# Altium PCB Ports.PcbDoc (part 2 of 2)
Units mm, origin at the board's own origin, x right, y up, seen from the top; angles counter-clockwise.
Board outline 100.96 x 99.82 mm, 2 copper layers (Top Layer, Bottom Layer); 116 components, 156 nets, 535 pads, 185 vias.
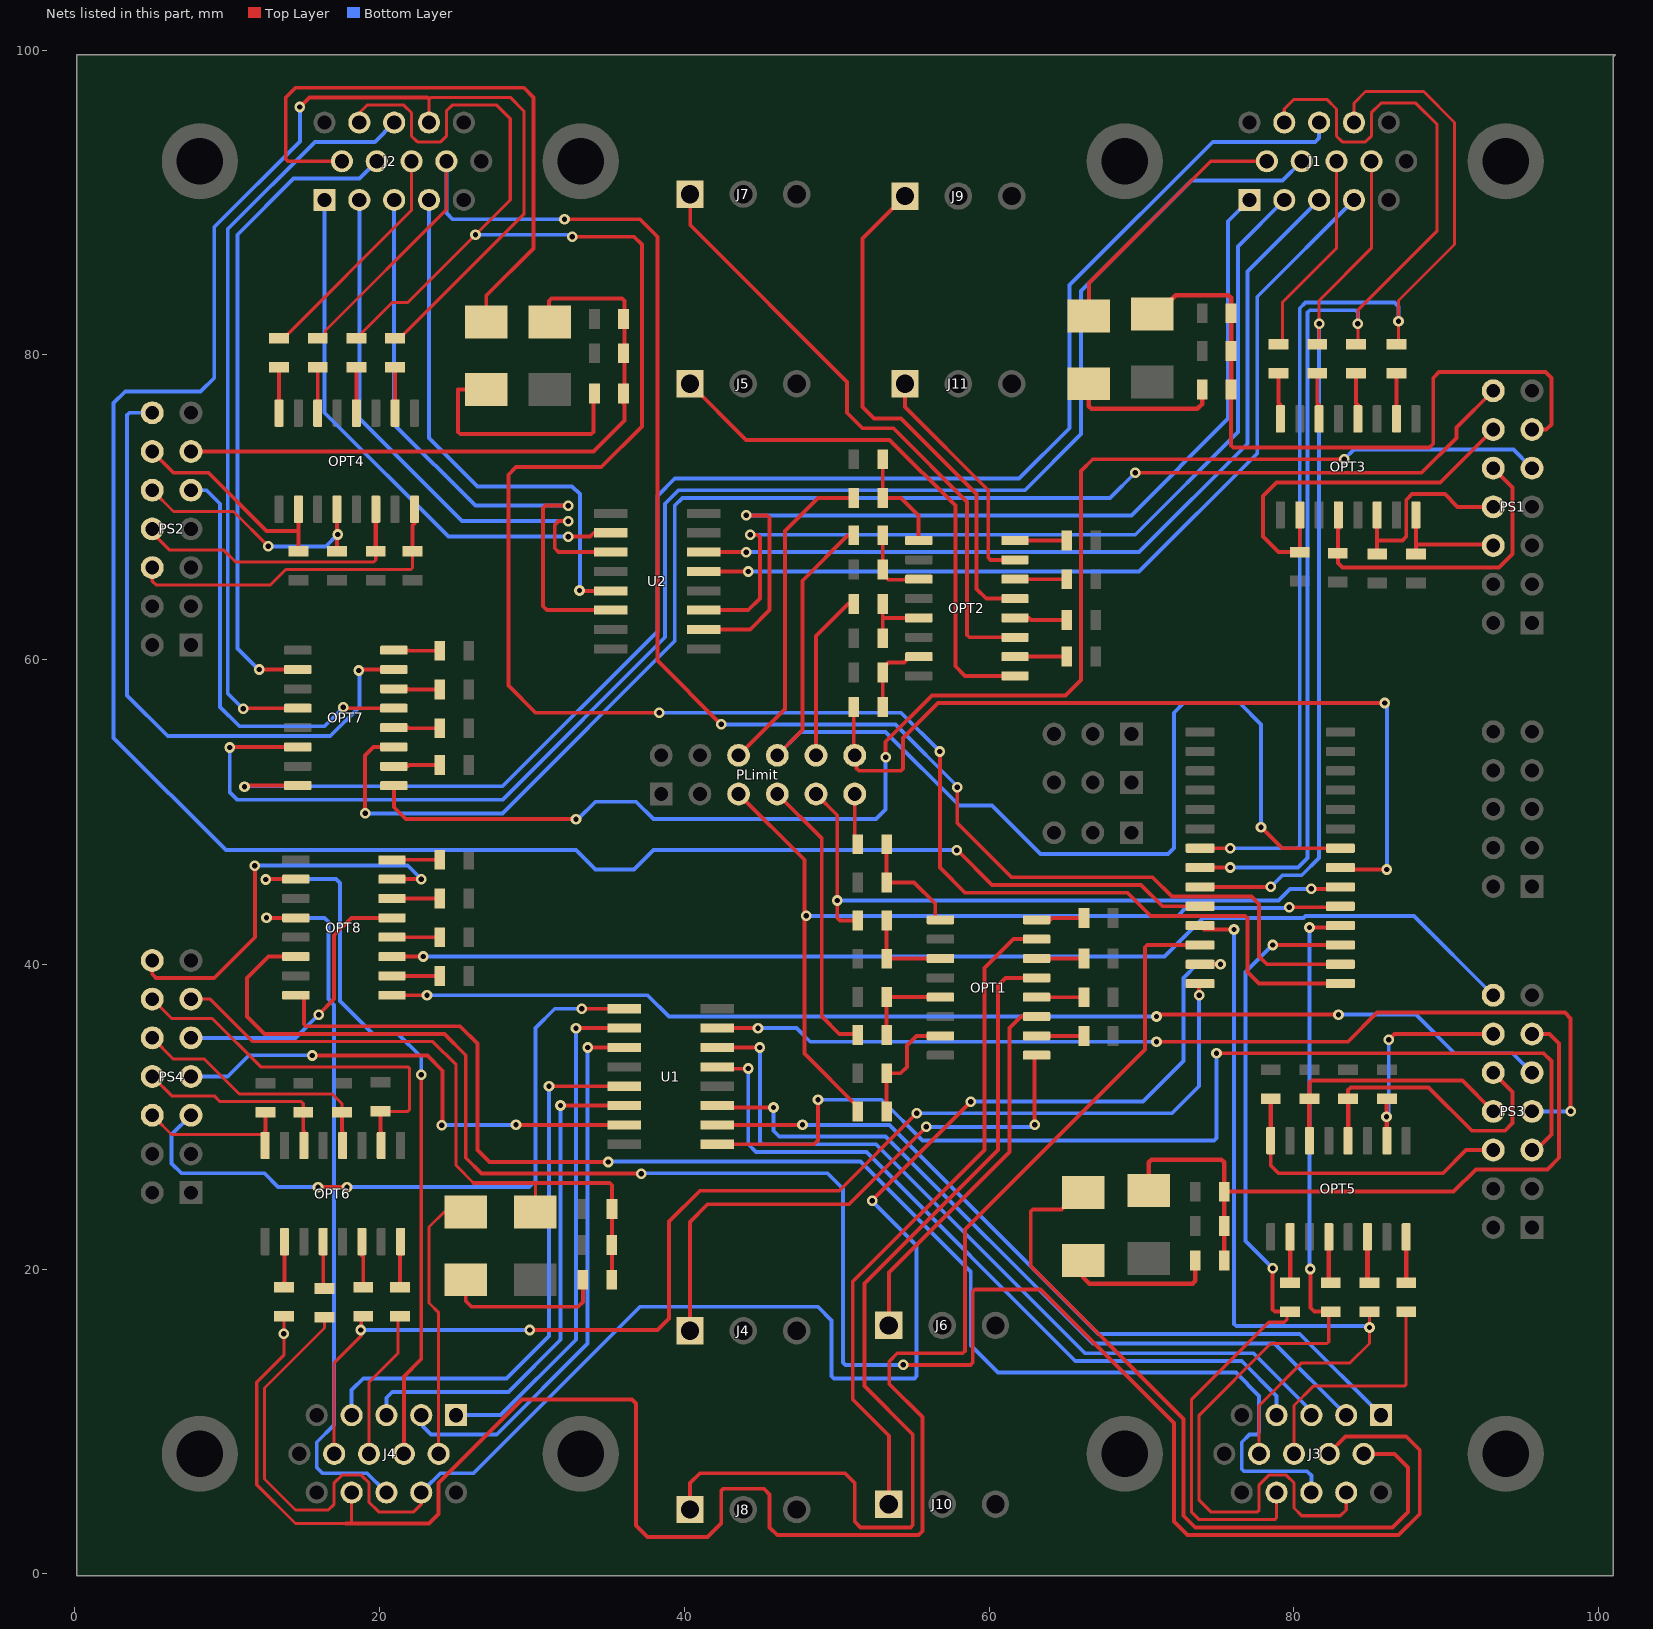
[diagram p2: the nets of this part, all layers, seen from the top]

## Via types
v1: diameter 0.7, hole 0.35, Top Layer to Bottom Layer, 151 vias
v2: diameter 0.9, hole 0.711, Top Layer to Bottom Layer, 29 vias
v3: diameter 4, hole 3, Top Layer to Bottom Layer, 4 vias
v4: diameter 1.27, hole 0.711, Top Layer to Bottom Layer, 1 vias

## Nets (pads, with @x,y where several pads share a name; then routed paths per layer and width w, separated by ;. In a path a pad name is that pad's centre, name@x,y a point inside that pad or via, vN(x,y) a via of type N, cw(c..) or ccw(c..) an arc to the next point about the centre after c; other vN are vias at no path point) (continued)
MCU_S3_DR: PS3.7 U1.7 | length 66
  Top Layer w0.254: U1.7@42.164,35.814 v1(44.831,35.814) ; v1(70.993,34.925) 83.566,34.925 85.471,36.83 97.79,36.83 98.171,36.449 v1(98.171,30.353)
  Bottom Layer w0.254: v1(44.831,35.814) 47.371,35.814 48.26,34.925 v1(70.993,34.925) ; PS3.7@95.631,30.353 v1(98.171,30.353)
MCU_S3_PLS: PS3.5 U1.1 | length 70.7
  Top Layer w0.254: U1.1@42.164,28.194 48.514,28.194 48.768,28.448 v1(48.768,31.115) ; v1(74.93,34.163) 96.393,34.163 96.901,33.655 96.901,28.829 PS3.5@95.885,27.813
  Bottom Layer w0.254: v1(48.768,31.115) 52.959,31.115 55.626,28.448 74.781,28.448 74.93,28.597 v1(74.93,34.163)
MCU_S4_DR: PS4.7 U1.15 | length 33.1
  Top Layer w0.254: v1(15.575,34.014) 23.136,34.014 24.13,33.02 v1@24.13,29.464 ; v1(28.956,29.464) U1.15@36.064,29.464
  Bottom Layer w0.254: PS4.7@7.62,32.639 10.033,32.639 11.43,34.036 15.553,34.036 v1(15.575,34.014) ; v1(24.084,29.442) 24.107,29.464 v1(28.956,29.464)
MCU_S4_PLS: PS4.5 U1.9 | length 44.7
  Top Layer w0.254: v1(15.956,25.378) 15.979,25.4 v1@17.78,25.4 ; v1(33.274,37.084) U1.9@36.064,37.084
  Bottom Layer w0.254: PS4.5@7.62,30.099 6.35,28.829 6.35,26.924 6.985,26.289 12.446,26.289 13.335,25.4 15.934,25.4 v1(15.956,25.378) ; v1(17.861,25.378) 29.823,25.378 30.226,25.781 30.226,35.814 31.496,37.084 v1(33.274,37.084)
NetD5_2: D5.2 R57.2 | length 10.1
  Top Layer w0.3: D5.2@66.548,78.105 66.548,76.63 66.724,76.454 73.66,76.454 73.98,76.774 R57.2@73.98,77.724
NetD6_2: D6.2 R58.2 | length 16.3
  Top Layer w0.254: D6.2@26.998,77.724 25.146,77.724 25.146,74.952 25.295,74.803 33.887,74.803 34.036,74.952 R58.2@34.036,77.644
NetD7_2: D7.2 R59.2 | length 10.1
  Top Layer w0.3: D7.2@66.167,20.574 66.167,19.469 66.585,19.051 73.356,19.051 73.532,19.227 R59.2@73.532,20.574
NetD8_2: D8.2 R60.2 | length 10.8
  Top Layer w0.254: D8.2@25.654,19.304 25.654,17.907 26.035,17.526 33.02,17.526 33.34,17.846 R60.2@33.34,19.304
NetJ4_1: J4.1@40.371,15.951 OPT1.1 | length 37
  Top Layer w0.254: J4.1@40.371,15.951 40.371,23.099 41.529,24.257 50.8,24.257 v1(55.88,29.337) ; v1(62.992,29.464) 62.992,33.909 OPT1.1@63.119,34.036
  Bottom Layer w0.254: v1(55.88,29.337) 62.865,29.337 v1(62.992,29.464)
NetJ5_1: J5.1 OPT2.1 | length 35.4
  Top Layer w0.254: J5.1@40.371,78.105 44.054,74.422 53.467,74.422 57.785,70.104 57.785,59.563 58.42,58.928 OPT2.1@61.702,58.928
NetJ6_1: J6.1 OPT1.3 | length 24.9
  Top Layer w0.254: J6.1@53.421,16.301 53.421,19.766 61.341,27.686 61.341,35.814 62.103,36.576 OPT1.3@63.119,36.576
NetJ7_1: J7.1 OPT2.3 | length 40.9
  Top Layer w0.254: J7.1@40.371,90.551 40.386,90.536 40.386,88.519 50.673,78.232 50.673,76.2 51.689,75.184 53.721,75.184 58.547,70.358 58.547,61.617 58.696,61.468 OPT2.3@61.702,61.468
NetJ8_1: J8.1 OPT1.5 | length 62.4
  Top Layer w0.254: J8.1@40.371,4.572 40.371,5.954 41.021,6.604 50.546,6.604 51.181,5.969 51.181,3.429 51.562,3.048 54.842,3.048 54.991,3.197 54.991,9.144 51.816,12.319 51.816,19.05 60.579,27.813 60.579,38.608 61.087,39.116 OPT1.5@63.119,39.116
NetJ9_1: J9.1 OPT2.5 | length 33.9
  Top Layer w0.254: J9.1@54.483,90.424 51.689,87.63 51.689,76.581 52.451,75.819 54.229,75.819 59.182,70.866 59.182,64.643 59.817,64.008 OPT2.5@61.702,64.008
NetJ10_1: J10.1 OPT1.7 | length 44
  Top Layer w0.254: J10.1@53.421,4.572 53.421,9.063 51.054,11.43 51.054,19.177 59.69,27.813 59.69,39.751 61.595,41.656 OPT1.7@63.119,41.656
NetJ11_1: J11.1 OPT2.7 | length 15.5
  Top Layer w0.254: J11.1@54.483,78.105 54.483,76.581 59.944,71.12 59.944,66.697 60.093,66.548 OPT2.7@61.702,66.548
NetOPT1_2: OPT1.2 R1.2 | length 3.1
  Top Layer w0.254: OPT1.2@63.119,35.306 64.307,35.306 R1.2@66.233,35.306
NetOPT1_4: OPT1.4 R5.2 | length 3.1
  Top Layer w0.254: OPT1.4@63.119,37.846 R5.2@66.233,37.846
NetOPT1_6: OPT1.6 R9.2 | length 3.1
  Top Layer w0.254: OPT1.6@63.119,40.386 R9.2@66.233,40.386
NetOPT1_8: OPT1.8 R14.2 | length 3.2
  Top Layer w0.254: OPT1.8@63.119,42.926 64.044,42.926 64.171,43.053 R14.2@66.233,43.053
NetOPT1_9: OPT1.9 R13.1 R71.1 | length 7.6
  Top Layer w0.254: R71.1@53.274,47.879 53.274,46.051 R13.1@53.274,45.375 55.082,45.375 56.471,43.986 56.471,43.094 56.639,42.926 OPT1.9@56.809,42.926
NetOPT1_11: OPT1.11 R10.1 R68.1 | length 6
  Top Layer w0.254: R68.1@53.274,42.872 R10.1@53.274,40.368 53.649,40.368 53.668,40.386 OPT1.11@56.809,40.386
NetOPT1_13: OPT1.13 R6.1 R65.1 | length 6.7
  Top Layer w0.254: OPT1.13@56.809,37.846 55.884,37.846 55.865,37.864 R6.1@53.274,37.864 53.274,36.036 ; 53.274,36.036 R65.1@53.274,35.36 53.274,36.036
NetOPT1_15: OPT1.15 R2.1 R8.1 | length 7.9
  Top Layer w0.254: R8.1@53.274,30.353 R2.1@53.274,32.857 54.193,32.857 54.61,33.274 54.61,34.671 55.245,35.306 OPT1.15@56.809,35.306
NetOPT2_2: OPT2.2 R3.2 | length 3.4
  Top Layer w0.254: OPT2.2@61.702,60.198 R3.2@65.09,60.198
NetOPT2_4: OPT2.4 R7.2 | length 3.4
  Top Layer w0.254: OPT2.4@61.702,62.738 62.627,62.738 62.754,62.611 R7.2@65.09,62.611
NetOPT2_6: OPT2.6 R11.2 | length 3.4
  Top Layer w0.254: OPT2.6@61.702,65.278 R11.2@65.09,65.278
NetOPT2_8: OPT2.8 R16.2 | length 3.4
  Top Layer w0.254: OPT2.8@61.702,67.818 R16.2@65.09,67.818
NetOPT2_9: OPT2.9 R70.1 R72.1 | length 7
  Top Layer w0.254: R70.1@53.02,73.152 R72.1@53.02,70.612 54.229,70.612 55.372,69.469 55.372,67.838 OPT2.9@55.392,67.818
NetOPT2_11: OPT2.11 R67.1 R69.1 | length 5.1
  Top Layer w0.254: R69.1@53.02,68.167 R67.1@53.02,65.913 53.02,65.613 53.388,65.245 54.45,65.245 54.483,65.278 OPT2.11@55.392,65.278
NetOPT2_13: OPT2.13 R15.1 R66.1 | length 5.2
  Top Layer w0.254: R15.1@53.02,61.405 53.02,62.804 ; R66.1@53.02,63.366 53.02,62.804 ; R66.1@53.02,63.659 53.02,62.804 ; OPT2.13@55.392,62.738 53.086,62.738 53.02,62.804
NetOPT2_15: OPT2.15 R4.1 R12.1 | length 5.2
  Top Layer w0.254: R12.1@53.02,56.896 R4.1@53.02,59.15 53.02,59.45 53.388,59.818 54.407,59.818 54.787,60.198 OPT2.15@55.392,60.198
NetOPT3_2: OPT3.2 R19.2 | length 3
  Top Layer w0.254: OPT3.2@86.741,75.801 R19.2@86.741,78.806
NetOPT3_4: OPT3.4 R23.2 | length 3.1
  Top Layer w0.254: R23.2@84.074,78.806 84.074,76.854 84.201,76.727 OPT3.4@84.201,75.801
NetOPT3_6: OPT3.6 R27.2 | length 3.1
  Top Layer w0.254: R27.2@81.534,78.806 81.534,76.854 81.661,76.727 OPT3.6@81.661,75.801
NetOPT3_8: OPT3.8 R31.2 | length 3.1
  Top Layer w0.254: R31.2@78.994,78.806 78.994,76.854 79.121,76.727 OPT3.8@79.121,75.801
NetOPT4_2: OPT4.2 R20.2 | length 3
  Top Layer w0.254: OPT4.2@21.018,76.18 R20.2@21.018,79.187
NetOPT4_4: OPT4.4 R24.2 | length 3
  Top Layer w0.254: OPT4.4@18.479,76.18 R24.2@18.479,79.187
NetOPT4_6: OPT4.6 R28.2 | length 3
  Top Layer w0.254: OPT4.6@15.938,76.18 R28.2@15.938,79.187
NetOPT4_8: OPT4.8 R32.2 | length 3
  Top Layer w0.254: OPT4.8@13.399,76.18 R32.2@13.399,79.187
NetOPT5_2: OPT5.2 R35.2 | length 3
  Top Layer w0.3: R35.2@79.756,19.111 OPT5.2@79.756,22.115
NetOPT5_4: OPT5.4 R39.2 | length 3.1
  Top Layer w0.3: OPT5.4@82.296,22.115 82.296,19.238 R39.2@82.423,19.111
NetOPT5_6: OPT5.6 R43.2 | length 3.1
  Top Layer w0.3: OPT5.6@84.836,22.115 84.836,19.238 R43.2@84.963,19.111
NetOPT5_8: OPT5.8 R47.2 | length 3
  Top Layer w0.3: R47.2@87.376,19.111 OPT5.8@87.376,22.115
NetOPT6_2: OPT6.2 R36.2 | length 3
  Top Layer w0.254: R36.2@13.716,18.798 13.716,19.174 13.757,19.214 OPT6.2@13.757,21.802
NetOPT6_4: OPT6.4 R40.2 | length 3.1
  Top Layer w0.254: OPT6.4@16.297,21.802 16.297,18.816 R40.2@16.383,18.73
NetOPT6_6: OPT6.6 R44.2 | length 3
  Top Layer w0.254: OPT6.6@18.837,21.802 18.837,20.877 18.923,20.791 R44.2@18.923,18.798
NetOPT6_8: OPT6.8 R48.2 | length 3
  Top Layer w0.254: R48.2@21.336,18.798 21.336,20.836 21.377,20.877 OPT6.8@21.377,21.802
NetOPT7_2: OPT7.2 R49.2 | length 3
  Top Layer w0.254: OPT7.2@20.938,53 21.863,53 21.949,53.086 R49.2@23.942,53.086
NetOPT7_4: OPT7.4 R51.2 | length 3
  Top Layer w0.254: OPT7.4@20.938,55.54 21.863,55.54 21.904,55.499 R51.2@23.942,55.499
NetOPT7_6: OPT7.6 R53.2 | length 3
  Top Layer w0.254: OPT7.6@20.938,58.08 21.863,58.08 21.904,58.039 R53.2@23.942,58.039
NetOPT7_8: OPT7.8 R55.2 | length 3
  Top Layer w0.254: OPT7.8@20.938,60.62 21.863,60.62 21.904,60.579 R55.2@23.942,60.579
NetOPT8_2: OPT8.2 R50.2 | length 3.1
  Top Layer w0.254: OPT8.2@20.811,39.243 R50.2@23.942,39.243
NetOPT8_4: OPT8.4 R52.2 | length 3.1
  Top Layer w0.254: OPT8.4@20.811,41.783 R52.2@23.942,41.783
NetOPT8_6: OPT8.6 R54.2 | length 3.1
  Top Layer w0.254: OPT8.6@20.811,44.323 R54.2@23.942,44.323
NetOPT8_8: OPT8.8 R56.2 | length 3.1
  Top Layer w0.254: OPT8.8@20.811,46.863 R56.2@23.942,46.863
S1_ALR: ?.22 J1.12 R23.1 | length 79.8
  Top Layer w0.203: J1.12@79.375,95.25 79.375,96.139 80.01,96.774 82.169,96.774 82.804,96.139 82.804,94.361 83.185,93.98 84.709,93.98 85.09,94.361 85.09,95.885 85.725,96.52 88.011,96.52 89.408,95.123 89.408,88.138 84.201,82.931 v1(84.201,82.042) 84.201,80.833 R23.1@84.074,80.706
  Top Layer w0.254: ?.22@73.848,46.355 v1(75.819,46.355)
  Bottom Layer w0.254: v1(75.819,46.355) 80.264,46.355 80.899,46.99 80.899,82.782 81.048,82.931 84.052,82.931 84.201,82.782 v1(84.201,82.042)
S1_ALR_CLR: J1.7 OPT7.14 | length 106
  Top Layer w0.254: v1(10.16,54.229) 10.201,54.27 OPT7.14@14.628,54.27
  Bottom Layer w0.254: v1(10.16,54.229) 10.16,51.308 10.668,50.8 28.067,50.8 38.735,61.468 38.735,70.231 39.624,71.12 62.357,71.12 66.04,74.803 66.04,84.201 73.279,91.44 79.248,91.44 J1.7@80.518,92.71
S1_ALR_CLR_MCU: OPT7.3 PS1.14 | length 97.1
  Top Layer w0.254: v1(19.05,49.911) 19.05,53.713 19.606,54.27 OPT7.3@20.938,54.27 ; v1(69.596,72.263) 88.392,72.263 90.678,74.549 90.678,75.234 PS1.14@93.091,77.647
  Bottom Layer w0.254: v1(19.05,49.911) 28.067,49.911 39.37,61.214 39.37,70.104 39.878,70.612 67.945,70.612 v1(69.596,72.263)
S1_ALR_MCU: OPT3.14 PS1.8 R21.1 | length 13.2
  Top Layer w0.254: R21.1@85.471,66.929 OPT3.14@85.471,69.492 ; 85.471,67.818 87.122,67.818 87.376,68.072 87.376,70.485 87.757,70.866 89.916,70.866 90.755,70.027 PS1.8@93.091,70.027
S1_DOWN_SENSOR: ?.5 PLimit.5 R8.2 | length 59.4
  Top Layer w0.254: PLimit.5@43.561,51.181 47.879,46.863 47.879,43.18 47.879,34.148 51.374,30.653 R8.2@51.374,30.353 ; v1(79.692,43.752) 82.995,43.752 ?.5@83.058,43.815
  Bottom Layer w0.254: v1(48.006,43.18) 72.39,43.18 72.898,43.688 79.629,43.688 v1(79.692,43.752)
S1_DR+: J1.3 U2.6 | length 56.8
  Top Layer w0.254: U2.6@41.279,67.056 41.406,67.183 41.66,66.929 41.787,67.056 v1(44.069,67.056)
  Bottom Layer w0.254: v1(44.069,67.056) 69.85,67.056 76.962,74.168 76.962,85.471 J1.3@81.661,90.17
S1_DR-: J1.4 U2.5 | length 58.8
  Top Layer w0.254: U2.5@41.279,65.786 v1(44.196,65.786)
  Bottom Layer w0.254: v1(44.196,65.786) 69.85,65.786 77.597,73.533 77.597,83.82 J1.4@83.947,90.17
S1_ON: J1.13 OPT7.16 | length 103.6
  Top Layer w0.254: v1(11.13,51.667) 11.194,51.73 OPT7.16@14.628,51.73
  Bottom Layer w0.254: v1@11.049,51.689 28.067,51.689 38.227,61.849 38.227,70.739 39.37,71.882 61.976,71.882 65.278,75.184 65.278,84.582 74.676,93.98 81.407,93.98 81.661,94.234 81.661,94.996 81.788,95.123 J1.13@81.661,95.25
S1_ON_MCU: OPT7.1 PS1.9 | length 98.6
  Top Layer w0.254: OPT7.1@20.938,51.73 20.938,50.309 21.717,49.53 v1(32.893,49.53) ; v1(53.213,53.594) 53.213,54.61 56.261,57.658 65.024,57.658 66.04,58.674 66.04,72.39 66.802,73.152 v1(83.312,73.152)
  Bottom Layer w0.254: v1(32.893,49.53) 33.014,49.53 34.157,50.673 36.83,50.673 37.973,49.53 52.578,49.53 53.213,50.165 v1(53.213,53.594) ; v1(83.312,73.152) 83.947,73.787 94.411,73.787 95.581,72.617 95.581,72.567 PS1.9@95.631,72.567
S1_PLS+: J1.1 U2.2 | length 61.7
  Top Layer w0.254: U2.2@41.279,61.976 44.323,61.976 45.593,63.246 45.593,69.32 45.444,69.469 v1(44.069,69.469)
  Bottom Layer w0.254: v1(44.069,69.469) 69.342,69.469 75.692,75.819 75.692,88.773 J1.1@77.089,90.17
S1_PLS-: J1.2 U2.3 | length 60
  Top Layer w0.254: U2.3@41.279,63.246 44.196,63.246 44.958,64.008 44.958,68.05 44.809,68.199 v1(44.323,68.199)
  Bottom Layer w0.254: v1(44.323,68.199) 69.596,68.199 76.327,74.93 76.327,87.122 J1.2@79.375,90.17
S1_SRV_RDY: ?.21 J1.14 R19.1 | length 74.8
  Top Layer w0.203: J1.14@83.947,95.25 83.947,96.52 84.709,97.282 88.519,97.282 90.551,95.25 90.551,87.249 86.868,83.566 v1(86.868,82.2) 86.868,80.833 R19.1@86.741,80.706
  Top Layer w0.254: ?.21@73.848,47.625 v1(75.819,47.625)
  Bottom Layer w0.254: v1(75.819,47.625) 80.242,47.625 80.391,47.774 80.391,83.058 80.772,83.439 86.614,83.439 86.868,83.185 v1(86.868,82.2)
S1_SRV_RDY_MCU: OPT3.16 PS1.6 R17.1 | length 7.7
  Top Layer w0.254: R17.1@88.011,66.929 OPT3.16@88.011,69.492 ; 88.011,67.564 93.014,67.564 PS1.6@93.091,67.487
S1_TRQ_ADC: D5.1 J1.6 | length 17.3
  Top Layer w0.254: D5.1@66.548,82.55 66.548,84.709 74.549,92.71 77.978,92.71 78.105,92.583 J1.6@78.232,92.71
S1_TRQ_ADC_M: C1.2 D1.2 PS1.11 R57.1 R61.2 | length 45.9
  Top Layer w0.254: R57.1@75.88,77.724 75.88,74.063 76.029,73.914 88.9,73.914 89.154,74.168 89.154,78.486 89.535,78.867 96.52,78.867 96.901,78.486 96.901,75.438 96.57,75.107 95.985,75.107 95.808,74.93 PS1.11@95.631,75.107
  Top Layer w0.3: D1.2@70.704,82.677 71.021,82.677 72.263,83.919 75.704,83.919 75.88,83.743 C1.2@75.88,82.739 R61.2@75.88,80.264 R57.1@75.88,77.724
S1_TRQ_IN_LM: J1.8 R31.1 | length 13.6
  Top Layer w0.203: R31.1@78.994,80.706 79,80.706 79.248,80.954 79.248,83.439 82.804,86.995 J1.8@82.804,92.71
S1_TRQ_IN_LM_MCU: OPT3.10 PS1.12 R29.1 | length 24.9
  Top Layer w0.254: OPT3.10@80.391,69.492 R29.1@80.391,67.056 78.994,67.056 77.978,68.072 77.978,70.739 78.867,71.628 89.612,71.628 PS1.12@93.091,75.107
S1_UP_SENSOR: PLimit.7 R65.2 | length 18.7
  Top Layer w0.254: PLimit.7@46.101,51.181 49.022,48.26 49.022,36.576 50.165,35.433 51.301,35.433 R65.2@51.374,35.36
S1_Z_OUT: ?.23 J1.9 R27.1 | length 57.1
  Top Layer w0.203: R27.1@81.534,80.706 81.661,80.833 v1(81.661,82.042) 81.661,83.566 85.09,86.995 J1.9@85.09,92.71
  Top Layer w0.254: ?.23@73.848,45.085 v1(78.486,45.085)
  Bottom Layer w0.254: v1(78.486,45.085) 79.248,45.847 80.518,45.847 81.661,46.99 v1(81.661,82.042)
S1_Z_OUT_MCU: OPT3.12 PS1.10 R25.1 | length 21.4
  Top Layer w0.254: OPT3.12@82.931,69.492 82.931,68.566 82.889,68.524 R25.1@82.889,66.99 82.889,66.336 83.185,66.04 93.472,66.04 94.361,66.929 94.361,71.297 93.268,72.39 93.091,72.39 PS1.10@93.091,72.567
S2_ALR: ?.1 J2.12 R24.1 | length 150.5
  Top Layer w0.203: R24.1@18.479,81.087 20.831,83.439 21.844,83.439 v1(26.289,87.884) 28.575,90.17 28.575,95.504 27.686,96.393 24.765,96.393 24.384,96.012 24.384,94.361 24.003,93.98 22.479,93.98 22.098,94.361 22.098,95.885 21.59,96.393 19.177,96.393 18.783,95.999 18.783,95.364 J2.12@18.669,95.25
  Top Layer w0.254: v1(32.639,87.757) 36.703,87.757 37.211,87.249 37.211,75.311 34.544,72.644 28.956,72.644 28.448,72.136 28.448,58.293 30.226,56.515 v1(38.354,56.515) ; v1(56.769,53.975) 56.769,46.353 58.418,44.704 69.088,44.704 70.612,43.18 76.813,43.18 76.962,43.031 76.962,39.497 77.724,38.735 ?.1@83.058,38.735
  Bottom Layer w0.254: v1(26.289,87.884) 32.512,87.884 v1(32.639,87.757) ; v1(38.354,56.515) 54.229,56.515 v1(56.769,53.975)
S2_ALR_CLR: J2.7 OPT7.10 | length 43
  Top Layer w0.254: v1(12.106,59.35) OPT7.10@14.628,59.35
  Bottom Layer w0.254: v1(12.106,59.35) 12.056,59.35 11.684,59.722 10.668,60.738 10.668,87.884 14.351,91.567 18.669,91.567 19.558,92.456 19.812,92.456 J2.7@19.812,92.71
S2_ALR_CLR_MCU: OPT7.7 PS2.14 | length 42
  Top Layer w0.254: v1(18.623,59.287) 18.687,59.35 OPT7.7@20.938,59.35
  Bottom Layer w0.254: PS2.14@5.08,76.2 3.578,76.2 3.429,76.051 3.429,57.658 6.096,54.991 16.764,54.991 18.669,56.896 v1@18.669,59.309
S2_ALR_MCU: OPT4.14 PS2.8 R22.1 | length 19.1
  Top Layer w0.203: PS2.8@5.08,68.58 5.08,68.326 6.223,67.183 9.779,67.183 10.541,66.421 19.629,66.421 19.748,66.54 R22.1@19.748,67.117
  Top Layer w0.3: R22.1@19.748,67.117 OPT4.14@19.748,69.87
S2_DOWN_SENSOR: ?.6 PLimit.9 R68.2 | length 43.5
  Top Layer w0.254: PLimit.9@48.641,51.181 50.038,49.784 v1(50.038,44.196) 50.038,43.053 50.219,42.872 R68.2@51.374,42.872 ; v1(81.153,44.958) 82.931,44.958 ?.6@83.058,45.085
  Bottom Layer w0.254: v1(50.038,44.196) 78.994,44.196 79.756,44.958 v1(81.153,44.958)
S2_DR+: J2.3 U2.14 | length 41.1
  Top Layer w0.254: v1(32.385,70.104) 30.883,70.104 30.734,69.955 30.734,63.5 30.988,63.246 U2.14@35.179,63.246
  Bottom Layer w0.254: J2.3@20.955,90.17 20.955,75.438 26.289,70.104 v1(32.385,70.104)
S2_DR-: J2.4 U2.13 | length 35.5
  Top Layer w0.254: v1(33.121,64.533) 33.138,64.516 U2.13@35.179,64.516
  Bottom Layer w0.254: J2.4@23.241,90.17 23.241,74.549 26.416,71.374 32.639,71.374 33.147,70.866 33.147,64.559 v1(33.121,64.533)
S2_ON: J2.13 OPT7.12 | length 49.3
  Top Layer w0.254: v1(11.049,56.769) 11.09,56.81 OPT7.12@14.628,56.81
  Bottom Layer w0.254: v1(11.049,56.769) 10.033,57.785 10.033,88.265 15.748,93.98 19.685,93.98 J2.13@20.955,95.25
S2_ON_MCU: OPT7.5 PS2.9 | length 28
  Top Layer w0.254: v1(17.607,56.874) 17.671,56.81 OPT7.5@20.938,56.81
  Bottom Layer w0.254: PS2.9@7.62,71.12 8.636,71.12 9.525,70.231 9.525,56.896 10.795,55.626 16.383,55.626 v1@17.526,56.769
S2_PLS+: J2.1 U2.10 | length 36.2
  Top Layer w0.254: v1(32.385,68.072) 33.8,68.072 34.054,68.326 U2.10@35.179,68.326
  Bottom Layer w0.254: J2.1@16.383,90.17 16.383,76.2 24.511,68.072 v1(32.385,68.072)
S2_PLS-: J2.2 U2.11 | length 37.2
  Top Layer w0.254: v1(32.385,69.088) 31.75,69.088 31.496,68.834 31.496,67.31 31.75,67.056 U2.11@35.179,67.056
  Bottom Layer w0.254: J2.2@18.669,90.17 18.669,75.819 25.4,69.088 v1(32.385,69.088)
S2_SRV_RDY: ?.24 J2.14 R20.1 | length 161.9
  Top Layer w0.203: R20.1@21.018,81.087 21.318,81.087 29.464,89.233 29.464,96.012 28.575,96.901 23.36,96.901 23.241,96.782 J2.14@23.241,95.25
  Top Layer w0.254: v1(14.764,96.266) 15.399,96.901 23.122,96.901 23.241,96.782 ; v1(57.88,47.498) 57.912,47.498 60.198,45.212 69.977,45.212 71.374,43.815 ?.24@73.848,43.815
  Bottom Layer w0.254: v1(14.764,96.266) 14.764,94.012 9.144,88.392 9.144,78.486 8.255,77.597 3.302,77.597 2.54,76.835 2.54,54.864 9.906,47.498 32.893,47.498 34.163,46.228 36.703,46.228 37.973,47.498 v1(57.88,47.498)
S2_SRV_RDY_MCU: OPT4.16 PS2.6 R18.1 | length 22.4
  Top Layer w0.203: PS2.6@5.08,66.04 5.08,65.151 5.334,64.897 12.827,64.897 13.843,65.913 22.042,65.913 22.162,66.032 R18.1@22.162,67.117
  Top Layer w0.254: R18.1@22.162,67.117 22.162,68.818 22.288,68.945 OPT4.16@22.288,69.87
S2_TRQ_ADC: D6.1 J2.6 | length 40.6
  Top Layer w0.254: J2.6@17.526,92.71 13.992,92.71 13.843,92.859 13.843,96.901 14.478,97.536 29.464,97.536 30.099,96.901 30.099,86.995 26.998,83.894 D6.1@26.998,82.169
S2_TRQ_ADC_M: C2.2 D2.2 PS2.11 R58.1 R62.2 | length 43.9
  Top Layer w0.254: PS2.11@7.62,73.66 7.747,73.533 7.874,73.66 34.036,73.66 36.068,75.692 36.068,76.735 36.009,76.795 R58.1@36.009,77.47 ; D2.2@31.115,81.987 31.115,83.544 31.264,83.693 35.919,83.693 36.068,83.544 36.068,82.358 36.068,80.104 R58.1@36.068,77.443
S2_TRQ_IN_LM: J2.8 R32.1 | length 15.4
  Top Layer w0.203: R32.1@13.399,81.087 13.698,81.087 22.098,89.487 J2.8@22.098,92.71
S2_TRQ_IN_LM_MCU: OPT4.10 PS2.12 R30.1 | length 14.5
  Top Layer w0.254: PS2.12@5.08,73.66 6.477,72.263 8.763,72.263 12.573,68.453 14.668,68.453 ; R30.1@14.668,67.117 14.668,68.453 ; OPT4.10@14.668,69.87 14.668,68.453
S2_UP_SENSOR: PLimit.11 R71.2 | length 3.4
  Top Layer w0.254: PLimit.11@51.181,51.181 51.181,48.072 R71.2@51.374,47.879
S2_Z_OUT: ?.2 J2.9 R28.1 | length 117.5
  Top Layer w0.203: R28.1@15.938,81.087 16.202,81.087 16.451,81.335 16.451,81.599 24.384,89.532 J2.9@24.384,92.71
  Top Layer w0.254: v1(32.131,88.9) 37.084,88.9 38.227,87.757 38.227,59.944 v1(42.418,55.753) ; v1(57.912,51.633) 57.912,49.276 61.468,45.72 70.732,45.72 72.002,44.45 77.216,44.45 77.724,43.942 77.724,40.513 78.232,40.005 ?.2@83.058,40.005
  Bottom Layer w0.254: J2.9@24.384,92.71 24.384,89.303 24.787,88.9 v1(32.131,88.9) ; v1(42.418,55.753) 53.848,55.753 57.912,51.689 v1(57.912,51.633)
S2_Z_OUT_MCU: OPT4.12 PS2.10 R26.1 | length 16.8
  Top Layer w0.203: PS2.10@5.08,71.12 6.477,69.723 10.414,69.723 v1(12.7,67.437)
  Top Layer w0.254: R26.1@17.209,67.117 OPT4.12@17.209,69.87
  Bottom Layer w0.254: v1(12.7,67.437) 16.467,67.437 v1(17.246,68.216)
S3_ALR: ?.4 J3.12 R39.1 | length 62.2
  Top Layer w0.203: R39.1@82.423,17.211 82.296,17.084 82.296,15.232 82.177,15.113 78.486,15.113 73.787,10.414 73.787,4.826 74.549,4.064 77.605,4.064 77.724,4.183 77.724,5.842 78.359,6.477 79.502,6.477 80.01,5.969 80.01,4.318 80.518,3.81 83.058,3.81 83.439,4.191 J3.12@83.439,5.334
  Top Layer w0.254: v1(81.026,42.418) 82.423,42.418 82.677,42.672 82.931,42.418 ?.4@83.058,42.545 ; v1(81.089,20.002) 81.089,17.463 81.341,17.211 R39.1@82.423,17.211
  Bottom Layer w0.254: v1(81.026,42.418) 81.026,20.065 v1(81.089,20.002)
S3_ALR_CLR: J3.7 OPT8.14 | length 130.2
  Top Layer w0.254: OPT8.14@14.501,40.513 12.7,40.513 11.303,39.116 11.303,36.576 12.446,35.433 24.257,35.433 25.654,34.036 25.654,27.305 26.692,26.267 v1(37.165,26.267) ; v1(54.356,13.716) 58.779,13.716 58.928,13.865 58.928,18.52 59.077,18.669 63.373,18.669 72.136,9.906 72.136,3.429 73.025,2.54 86.868,2.54 88.265,3.937 88.265,8.128 87.376,9.017 83.395,9.017 82.296,7.918 J3.7@82.296,7.874
  Bottom Layer w0.254: v1@37.211,26.289 49.403,26.289 50.419,25.273 50.419,13.865 50.568,13.716 v1(54.356,13.716)
S3_ALR_CLR_MCU: OPT8.3 PS3.14 | length 75.5
  Top Layer w0.254: OPT8.3@20.811,40.513 v1(22.86,40.513)
  Bottom Layer w0.254: v1(22.86,40.513) 71.501,40.513 74.041,43.053 80.645,43.053 80.772,43.18 87.884,43.18 PS3.14@93.091,37.973
S3_ALR_MCU: OPT5.14 PS3.8 R37.1 | length 16.8
  Top Layer w0.254: R37.1@81.026,31.181 81.026,32.236 81.175,32.385 91.059,32.385 PS3.8@93.091,30.353
  Top Layer w0.3: OPT5.14@81.026,28.425 R37.1@81.026,31.181
S3_DOWN_SENSOR: ?.7 PLimit.12 R12.2 | length 55.9
  Top Layer w0.254: R12.2@51.12,56.896 51.12,53.782 PLimit.12@51.181,53.721 51.308,53.594 51.308,52.854 51.457,52.705 54.207,52.705 54.356,52.854 54.356,54.864 56.642,57.15 v1(85.979,57.15) ; ?.7@83.058,46.355 83.185,46.228 v1(86.106,46.228)
  Bottom Layer w0.254: v1(85.979,57.15) 86.106,57.023 v1(86.106,46.228)
S3_DR+: J3.3 U1.6 | length 52.8
  Top Layer w0.254: U1.6@42.164,34.544 v1(44.958,34.544)
  Bottom Layer w0.254: v1(44.958,34.544) 44.958,28.343 45.107,28.194 52.578,28.194 66.294,14.478 77.343,14.478 81.153,10.668 J3.3@81.153,10.414
S3_DR-: J3.4 U1.5 | length 49.8
  Top Layer w0.254: U1.5@42.164,33.274 42.291,33.147 44.179,33.147 v1(44.196,33.164)
  Bottom Layer w0.254: v1(44.196,33.164) 44.196,28.194 44.704,27.686 51.943,27.686 65.659,13.97 76.581,13.97 78.867,11.684 J3.4@78.867,10.414
S3_ON: J3.13 OPT8.16 | length 93.3
  Top Layer w0.254: OPT8.16@14.501,37.973 14.86,37.973 15.028,37.805 15.028,36.09 15.177,35.941 25.273,35.941 26.416,34.798 26.416,27.813 27.2,27.029 v1(35.006,27.029)
  Bottom Layer w0.254: v1@35.179,27.051 51.562,27.051 58.801,19.812 58.801,14.986 60.579,13.208 76.2,13.208 77.724,11.684 77.724,9.293 77.575,9.144 77.089,9.144 76.581,8.636 76.581,6.88 76.73,6.731 80.877,6.731 81.153,6.455 J3.13@81.153,5.334
S3_ON_MCU: OPT8.1 PS3.9 | length 77
  Top Layer w0.254: OPT8.1@20.811,37.973 v1(23.114,37.973) ; v1(70.993,36.576) 71.12,36.703 v1(82.931,36.703)
  Bottom Layer w0.254: v1(23.114,37.973) 37.592,37.973 38.989,36.576 v1(70.993,36.576) ; v1(82.931,36.703) 88.011,36.703 90.551,34.163 94.361,34.163 PS3.9@95.631,32.893
S3_PLS+: J3.1 U1.2 | length 51.5
  Top Layer w0.254: U1.2@42.164,29.464 v1(47.752,29.464)
  Bottom Layer w0.254: v1(47.752,29.464) 53.467,29.464 67.183,15.748 80.391,15.748 J3.1@85.725,10.414
S3_PLS-: J3.2 U1.3 | length 50.6
  Top Layer w0.254: U1.3@42.164,30.734 42.291,30.607 v1(45.847,30.607)
  Bottom Layer w0.254: v1(45.847,30.607) 45.847,29.083 46.228,28.702 53.213,28.702 66.802,15.113 78.74,15.113 J3.2@83.439,10.414
S3_SRV_RDY: ?.3 J3.14 R35.1 | length 55
  Top Layer w0.203: J3.14@78.867,5.334 78.867,3.675 78.748,3.556 73.787,3.556 73.279,4.064 73.279,11.43 78.359,16.51 79.375,16.51 79.54,16.675 79.54,16.995 R35.1@79.756,17.211
  Top Layer w0.254: v1(78.613,20.066) 78.613,17.36 78.762,17.211 R35.1@79.756,17.211 ; v1(78.613,41.275) ?.3@83.058,41.275
  Bottom Layer w0.254: v1(78.613,20.066) 76.835,21.844 76.835,39.497 v1(78.613,41.275)
S3_SRV_RDY_MCU: OPT5.16 PS3.6 R33.1 | length 19.8
  Top Layer w0.254: OPT5.16@78.486,28.425 78.486,26.797 78.994,26.289 89.789,26.289 91.313,27.813 PS3.6@93.091,27.813
  Top Layer w0.3: OPT5.16@78.486,28.425 R33.1@78.486,31.181
S3_TRQ_ADC: D7.1 J3.6 | length 49.7
  Top Layer w0.254: D7.1@66.167,25.019 65.849,25.019 64.752,23.922 62.887,23.922 62.738,23.773 62.738,20.193 72.771,10.16 72.771,3.81 73.533,3.048 86.487,3.048 87.503,4.064 87.503,6.985 86.614,7.874 J3.6@84.582,7.874
S3_TRQ_ADC_M: C3.2 D3.2 PS3.11 R59.1 R63.2 | length 45.8
  Top Layer w0.254: C3.2@75.432,25.083 90.488,25.083 91.948,26.543 96.647,26.543 97.409,27.305 97.409,34.798 96.774,35.433 PS3.11@95.631,35.433
  Top Layer w0.3: D3.2@70.485,25.146 70.485,27.002 70.661,27.178 75.256,27.178 75.432,27.002 C3.2@75.432,25.083 R63.2@75.432,22.828 R59.1@75.432,20.574
S3_TRQ_IN_LM: J3.8 R47.1 | length 15.9
  Top Layer w0.203: J3.8@80.01,7.874 80.01,11.049 81.28,12.319 87.257,12.319 87.376,12.438 R47.1@87.376,17.211
S3_TRQ_IN_LM_MCU: OPT5.10 PS3.12 R45.1 | length 14.9
  Top Layer w0.254: v1(86.233,35.052) 86.614,35.433 PS3.12@93.091,35.433
  Top Layer w0.3: OPT5.10@86.106,28.425 R45.1@86.106,31.181
  Bottom Layer w0.254: v1(86.08,29.989) 86.233,30.142 v1(86.233,35.052)
S3_UP_SENSOR: PLimit.10 R66.2 | length 11.2
  Top Layer w0.254: PLimit.10@48.641,53.721 48.641,61.555 50.745,63.659 R66.2@51.12,63.659
S3_Z_OUT: ?.25 J3.9 R43.1 | length 51.4
  Top Layer w0.203: J3.9@77.724,7.874 77.724,11.049 80.518,13.843 83.693,13.843 84.963,15.113 v1(84.963,16.162) R43.1@84.963,17.211
  Top Layer w0.254: ?.25@73.848,42.545 74.102,42.291 v1(76.073,42.291)
  Bottom Layer w0.254: v1(76.073,42.291) 76.073,16.405 76.222,16.256 84.591,16.256 84.6,16.247 84.878,16.247 v1(84.963,16.162)
S3_Z_OUT_MCU: OPT5.12 PS3.10 R41.1 | length 19.6
  Top Layer w0.254: R41.1@83.566,31.181 83.566,31.75 83.744,31.928 88.849,31.928 91.694,29.083 93.853,29.083 94.361,29.591 94.361,31.623 93.345,32.639 93.345,32.893 PS3.10@93.091,32.893
  Top Layer w0.3: OPT5.12@83.566,28.425 R41.1@83.566,31.181
S4_ALR: ?.27 J4.12 R40.1 | length 116.3
  Top Layer w0.203: R40.1@16.383,16.83 16.383,16.129 12.446,12.192 12.446,6.223 14.478,4.191 16.637,4.191 17.018,4.572 17.018,5.969 17.526,6.477 18.796,6.477 19.304,5.969 19.304,4.699 19.939,4.064 22.233,4.064 22.733,4.564 J4.12@22.733,5.334
  Top Layer w0.254: v1(52.324,24.479) 52.324,24.511 v1(58.801,30.988) ; ?.27@73.848,40.005 v1(75.184,40.005)
  Bottom Layer w0.254: J4.12@22.733,5.334 22.987,5.334 22.987,5.588 24.003,6.604 26.162,6.604 37.084,17.526 48.768,17.526 49.657,16.637 49.657,12.976 49.806,12.827 55.096,12.827 55.245,12.976 55.245,21.558 v1(52.324,24.479) ; v1(58.801,30.988) 70.104,30.988 72.771,33.655 72.771,39.116 73.66,40.005 v1(75.184,40.005)
S4_ALR_CLR: J4.7 OPT8.10 | length 48.2
  Top Layer w0.254: v1(12.527,45.571) 12.55,45.593 OPT8.10@14.501,45.593 ; J4.7@21.59,7.874 21.59,12.954 22.733,14.097 v1(22.733,32.766)
  Bottom Layer w0.254: v1@12.446,45.593 17.145,45.593 17.399,45.339 17.399,37.592 19.558,35.433 21.209,35.433 22.733,33.909 v1(22.733,32.766)
S4_ALR_CLR_MCU: OPT8.7 PS4.14 | length 26.7
  Top Layer w0.254: PS4.14@5.08,40.259 5.08,39.37 5.334,39.116 9.144,39.116 11.811,41.783 v1(11.811,46.482) ; OPT8.7@20.811,45.593 v1(22.733,45.593)
  Bottom Layer w0.254: v1(11.811,46.482) 21.844,46.482 v1(22.733,45.593)
S4_ALR_MCU: OPT6.14 PS4.8 R38.1 | length 13.4
  Top Layer w0.203: PS4.8@5.08,32.639 6.35,31.369 9.144,31.369 9.525,30.988 14.867,30.988 14.986,30.869 R38.1@14.986,30.292
  Top Layer w0.254: R38.1@14.986,30.292 14.986,29.079 15.027,29.038 OPT6.14@15.027,28.112
S4_DOWN_SENSOR: ?.8 PLimit.8 R69.2 | length 74.9
  Top Layer w0.254: PLimit.8@46.101,53.721 47.752,55.372 47.752,65.175 50.745,68.167 R69.2@51.12,68.167 ; v1(77.851,49.009) 79.235,47.625 ?.8@83.058,47.625
  Bottom Layer w0.254: PLimit.8@46.101,53.721 47.625,55.245 53.213,55.245 58.039,50.419 60.198,50.419 63.373,47.244 71.755,47.244 72.136,47.625 72.136,56.515 72.771,57.15 76.454,57.15 77.851,55.753 v1(77.851,49.009)
S4_DR+: J4.3@20.447,10.414 U1.14 | length 33.7
  Top Layer w0.254: v1(31.877,30.734) U1.14@36.064,30.734
  Bottom Layer w0.254: J4.3@20.447,10.414 20.447,11.557 20.828,11.938 28.448,11.938 31.877,15.367 v1(31.877,30.734)
S4_DR-: J4.4 U1.13 | length 37.4
  Top Layer w0.254: v1(31.115,32.004) U1.13@36.064,32.004
  Bottom Layer w0.254: J4.4@18.161,10.414 18.161,12.065 18.923,12.827 28.321,12.827 31.115,15.621 v1(31.115,32.004)
S4_ON: J4.13 OPT8.12 | length 48.1
  Top Layer w0.254: v1(12.573,43.053) OPT8.12@14.501,43.053
  Bottom Layer w0.254: v1(12.573,43.053) 16.383,43.053 16.637,42.799 16.637,37.719 17.018,37.338 17.018,9.779 15.875,8.636 15.875,6.985 16.256,6.604 19.177,6.604 20.32,5.461 20.447,5.461 20.574,5.461 J4.13@20.447,5.334
S4_ON_MCU: OPT8.5 PS4.9 | length 18.9
  Top Layer w0.254: v1(16.002,36.703) 17.018,37.719 17.018,41.91 18.161,43.053 OPT8.5@20.811,43.053
  Bottom Layer w0.254: PS4.9@7.62,35.179 14.478,35.179 v1(16.002,36.703)
S4_PLS+: J4.1@25.019,10.414 U1.10 | length 33.5
  Top Layer w0.254: v1(32.893,35.814) U1.10@36.064,35.814
  Bottom Layer w0.254: J4.1@25.019,10.414 27.94,10.414 32.893,15.367 v1(32.893,35.814)
S4_PLS-: J4.2@22.733,10.414 U1.11 | length 36.1
  Top Layer w0.254: v1(33.655,34.544) U1.11@36.064,34.544
  Bottom Layer w0.254: J4.2@22.733,10.414 22.847,10.3 22.847,9.665 23.368,9.144 27.686,9.144 33.655,15.113 v1(33.655,34.544)
S4_SRV_RDY: ?.26 J4.14 R36.1 | length 129.1
  Top Layer w0.203: R36.1@13.716,16.898 v1(13.716,15.748) 13.716,14.351 11.938,12.573 11.938,5.842 14.478,3.302 17.78,3.302 ; 18.161,3.302 J4.14@18.161,5.334
  Top Layer w0.254: 17.78,3.302 18.161,3.302 23.241,3.302 23.876,3.937 23.876,5.969 29.337,11.43 36.576,11.43 36.83,11.176 36.83,3.175 37.592,2.413 41.529,2.413 42.418,3.302 42.418,5.439 42.567,5.588 45.212,5.588 45.593,5.207 45.593,3.048 46.101,2.54 55.372,2.54 55.626,2.794 55.626,10.287 53.445,12.468 53.445,13.948 53.975,14.478 58.271,14.478 58.42,14.627 58.42,22.606 70.231,34.417 70.231,41.126 70.38,41.275 ?.26@73.848,41.275
S4_SRV_RDY_MCU: OPT6.16 PS4.6 R34.1 | length 10.8
  Top Layer w0.203: PS4.6@5.08,30.099 5.08,29.972 5.207,29.972 6.342,28.837 12.293,28.837 12.487,28.644 OPT6.16@12.487,28.112
  Top Layer w0.254: OPT6.16@12.487,28.112 12.487,29.038 12.507,29.058 R34.1@12.507,30.292
S4_TRQ_ADC: D8.1 J4.6 | length 18
  Top Layer w0.203: J4.6@23.876,7.874 23.876,17.145 23.241,17.78 23.241,22.758 24.232,23.749 D8.1@25.654,23.749
S4_TRQ_ADC_M: C4.2 D4.2 PS4.11 R60.1 R64.2 | length 44.7
  Top Layer w0.203: PS4.11@7.62,37.719 8.89,37.719 11.684,34.925 23.495,34.925 25.019,33.401 25.019,26.797 26.162,25.654 ; D4.2@30.226,23.749 30.226,25.654
  Top Layer w0.254: 26.162,25.654 30.226,25.654 35.101,25.654 35.25,25.505 C4.2@35.25,23.938 35.25,22.275 35.24,22.265 R64.2@35.24,21.59 35.24,19.979 R60.1@35.24,19.304
S4_TRQ_IN_LM: J4.8 R48.1 | length 9.9
  Top Layer w0.203: J4.8@19.304,7.874 19.304,12.573 21.209,14.478 21.209,16.771 R48.1@21.336,16.898
S4_TRQ_IN_LM_MCU: OPT6.10 PS4.12 R46.1 | length 25.8
  Top Layer w0.203: PS4.12@5.08,37.719 5.334,37.719 5.334,37.465 6.35,36.449 9.017,36.449 12.192,33.274 21.852,33.274 21.971,33.155 21.971,30.472 21.852,30.353 R46.1@20.066,30.353
  Top Layer w0.254: R46.1@20.066,30.353 20.066,29.079 20.107,29.038 OPT6.10@20.107,28.112
S4_UP_SENSOR: PLimit.6 R72.2 | length 21.5
  Top Layer w0.254: PLimit.6@43.561,53.721 43.815,53.721 43.815,53.975 46.609,56.769 46.609,68.453 48.768,70.612 R72.2@51.12,70.612
S4_Z_OUT: ?.28 J4.9 R44.1 | length 81.9
  Top Layer w0.203: J4.9@17.018,7.874 17.018,13.843 18.796,15.621 18.796,16.002 18.796,16.771 R44.1@18.923,16.898
  Top Layer w0.254: v1(29.845,16.002) 38.227,16.002 38.989,16.764 38.989,23.114 41.021,25.146 50.165,25.146 v1(55.245,30.226) ; v1(73.787,37.973) 73.787,38.674 ?.28@73.848,38.735
  Bottom Layer w0.254: v1(18.773,16.002) v1(29.845,16.002) ; v1(55.245,30.226) 72.009,30.226 73.787,32.004 v1(73.787,37.973)
S4_Z_OUT_MCU: OPT6.12 PS4.10 R42.1 | length 17
  Top Layer w0.203: PS4.10@5.08,35.179 6.477,33.782 8.509,33.782 10.795,31.496 16.891,31.496 17.526,30.861 R42.1@17.526,30.292
  Top Layer w0.254: R42.1@17.526,30.292 17.526,29.079 17.567,29.038 OPT6.12@17.567,28.112
pads on no net: U1.4 U2.4

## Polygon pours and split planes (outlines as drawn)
no net on Top Layer "NONET_L01_P000" (solid, shelved, pour order 0): 0.127,99.695 100.838,99.695 100.965,99.568 100.965,0 0.254,0 0.127,0.127

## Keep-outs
Top Layer:
  lines w0.254: 100.965,99.568 101.092,99.695
Keep-Out Layer:
  lines w0.254: 100.965,99.568 100.965,-0.127 0.127,-0.127 0.127,99.187 0.127,99.695 101.092,99.695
